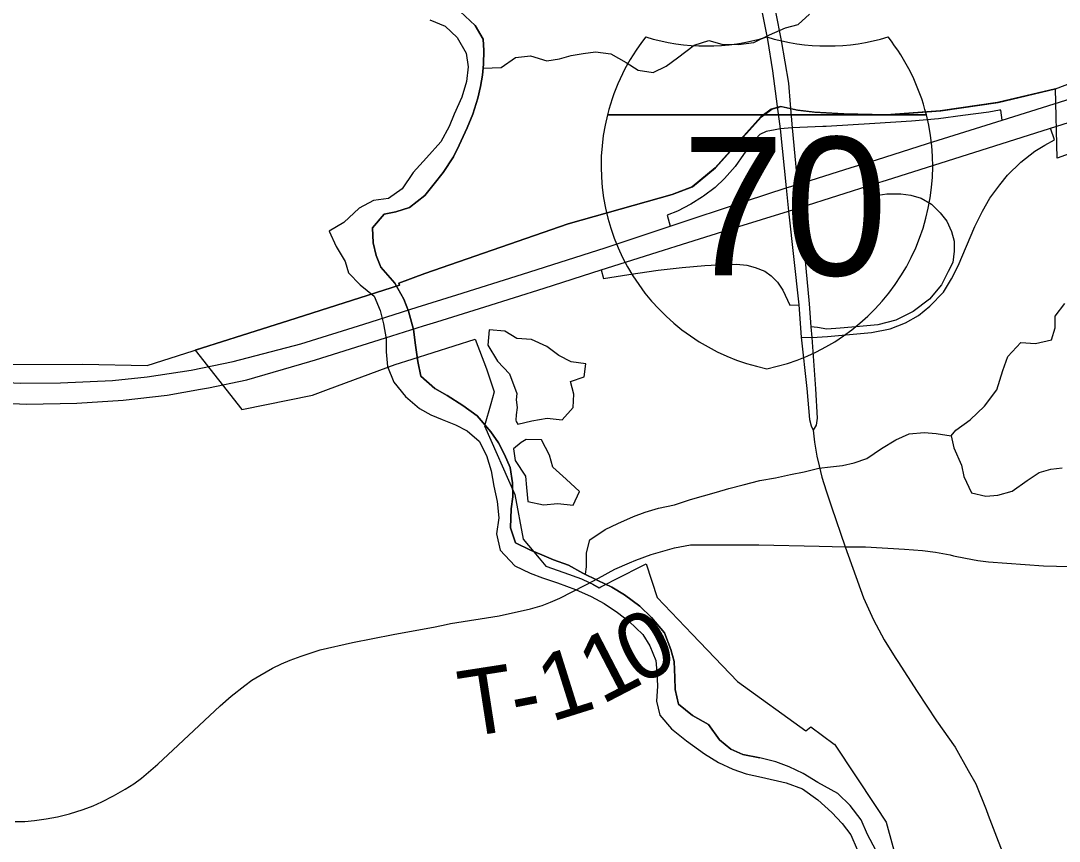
# Model space of a CAD drawing. Extents: x 0 to 34, y 0 to 26.1.
# Drawn here: x 24.227 to 25.117, y 17.231 to 17.933 of the extents above; entities that cross this region are included whole.
import ezdxf

# ---------------------------------------------------------------- set-up
doc = ezdxf.new("R2010")
doc.units = 0
for name, color, linetype in [('GM_X_Interchange_Ramps', 7, 'Continuous'), ('GM_X_Interstate_Location', 7, 'Continuous'), ('GM_X_Interstate_Route', 7, 'Continuous'), ('GM_X_Interstate_Shield', 7, 'Continuous'), ('GM_X_Minor_Lake', 7, 'Continuous'), ('GM_X_Minor_River', 7, 'Continuous'), ('GM_X_State_Route', 7, 'Continuous'), ('GM_X_Township_Road', 7, 'Continuous'), ('GM_X_Township_Road_Text', 7, 'Continuous'), ('SC_Scratch1', 7, 'Continuous')]:
    doc.layers.add(name, color=color, linetype=linetype)

msp = doc.modelspace()

# ---------------------------------------------------------------- linework, layer by layer
at = {"layer": 'GM_X_Interchange_Ramps'}
for p, q in [((24.88787, 17.8414), (24.8775, 17.84071)), ((25.11253, 17.83122), (25.10922, 17.84116))]:
    msp.add_line(p, q, dxfattribs=at)
for points in [[(25.06547, 17.85652), (25.05622, 17.85498), (25.03406, 17.85201), (25.01327, 17.84915), (24.99008, 17.84721), (24.95878, 17.84515), (24.9171, 17.8427)], [(25.06789, 17.84807), (25.0665, 17.85669), (25.06547, 17.85652)], [(24.8775, 17.84071), (24.87337, 17.8399), (24.86567, 17.83839), (24.86018, 17.83585), (24.85359, 17.82859), (24.84628, 17.81854), (24.83897, 17.80837), (24.82994, 17.79809), (24.82183, 17.79044), (24.81188, 17.78301)], [(24.9171, 17.8427), (24.91412, 17.84253), (24.88787, 17.8414)], [(24.89562, 17.66217), (24.90476, 17.66184), (24.91815, 17.66268), (24.95574, 17.66627), (24.97181, 17.66948), (24.98483, 17.67451), (24.99602, 17.68067), (25.00579, 17.68887), (25.01761, 17.70089), (25.02437, 17.7121), (25.03017, 17.72328), (25.04445, 17.75697), (25.05085, 17.77022), (25.05724, 17.7813), (25.06581, 17.79273), (25.07244, 17.80106), (25.08386, 17.81203), (25.09585, 17.82162), (25.10419, 17.82665), (25.11253, 17.83122)], [(24.95935, 17.79377), (24.96164, 17.78393), (24.96884, 17.78496), (24.98106, 17.78496), (24.9894, 17.78382), (24.99847, 17.78125), (25.0071, 17.77605), (25.01475, 17.76874), (25.02035, 17.76143), (25.02435, 17.75263), (25.02663, 17.7443), (25.02663, 17.73584), (25.02538, 17.72625)], [(24.81188, 17.78301), (24.81098, 17.78233), (24.80116, 17.77605), (24.78951, 17.77022), (24.78084, 17.76659), (24.78349, 17.75726)], [(24.72414, 17.71996), (24.72611, 17.71243), (24.74782, 17.71597), (24.77294, 17.71962), (24.7935, 17.72191), (24.81304, 17.72362), (24.82903, 17.72442), (24.84011, 17.72465), (24.8489, 17.72396), (24.85621, 17.72202), (24.86443, 17.71886), (24.86976, 17.71471), (24.87539, 17.70938), (24.87983, 17.70256), (24.88573, 17.68951), (24.89349, 17.68989)], [(25.02538, 17.72625), (25.02161, 17.71837), (25.0159, 17.70706), (25.0055, 17.69484), (24.99157, 17.68421), (24.97672, 17.67679), (24.96118, 17.67279), (24.94565, 17.67131), (24.92897, 17.66994), (24.91766, 17.66914), (24.90967, 17.67051), (24.90396, 17.67119)]]:
    msp.add_lwpolyline(points, dxfattribs=at)
at = {"layer": 'GM_X_Interstate_Route'}
for points in [[(25.06789, 17.84807), (25.15693, 17.87617), (25.22785, 17.89886), (25.29174, 17.91888), (25.38348, 17.94771), (25.44443, 17.96693), (25.52754, 17.99309), (25.59845, 18.0156), (25.67489, 18.03963), (25.75452, 18.0649), (25.81227, 18.08296), (25.85649, 18.09746), (25.896, 18.11232), (25.93026, 18.12665), (25.97711, 18.1485)], [(25.10827, 17.84086), (25.10922, 17.84116), (25.14617, 17.85289), (25.2016, 17.87048), (25.2888, 17.89815), (25.38383, 17.92805), (25.44176, 17.94611), (25.59178, 17.99322)], [(24.95998, 17.81419), (25.00391, 17.82805), (25.06789, 17.84807)], [(24.96878, 17.79677), (25.00932, 17.80966), (25.07329, 17.82968), (25.10827, 17.84086)], [(24.78349, 17.75726), (24.84882, 17.77903), (24.88284, 17.78998), (24.89237, 17.79296), (24.93851, 17.80741), (24.95998, 17.81419)], [(24.77767, 17.73672), (24.78838, 17.74008), (24.83848, 17.75583), (24.88471, 17.77026), (24.89458, 17.77337), (24.95935, 17.79377), (24.96878, 17.79677)], [(23.70781, 17.66191), (23.75214, 17.65819), (23.80544, 17.6541), (23.85589, 17.65009), (23.92512, 17.64485), (24.00805, 17.63871), (24.06073, 17.63461), (24.09899, 17.63159), (24.14846, 17.62785), (24.19286, 17.62465), (24.22685, 17.62296), (24.26111, 17.62313), (24.30578, 17.62509), (24.33549, 17.62829), (24.37296, 17.6339), (24.4089, 17.64129), (24.46692, 17.6565), (24.52084, 17.67341), (24.56675, 17.68782), (24.60057, 17.69841), (24.65689, 17.7163), (24.72754, 17.73872), (24.78349, 17.75726)], [(24.47943, 17.64286), (24.53959, 17.6616), (24.57208, 17.67186), (24.58355, 17.67548), (24.62466, 17.68829), (24.67538, 17.70431), (24.72414, 17.71996), (24.77767, 17.73672)], [(23.70606, 17.64373), (23.89929, 17.62858), (24.01461, 17.61986), (24.08117, 17.61497), (24.18341, 17.60714), (24.23208, 17.60483), (24.27514, 17.60563), (24.31492, 17.60821), (24.35256, 17.61257), (24.38108, 17.61759), (24.38797, 17.6188), (24.42071, 17.62574), (24.47473, 17.6414), (24.47943, 17.64286)]]:
    msp.add_lwpolyline(points, dxfattribs=at)
at = {"layer": 'GM_X_Interstate_Shield'}
for p, q in [((24.72959, 17.85274), (25.00284, 17.85274)), ((25.00284, 17.85274), (24.72959, 17.85274)), ((25.00284, 17.85274), (24.72959, 17.85274))]:
    msp.add_line(p, q, dxfattribs=at)
for centre, start, end in [((24.90173, 17.80921), 141.66896, 165.80665), ((24.81433, 18.08914), 253.00908, 286.99093), ((24.9181, 18.08914), 253.00908, 286.99093), ((24.83071, 17.80921), 14.19335, 38.33104), ((24.90173, 17.80921), 165.80665, 258.46304), ((24.83071, 17.80921), 281.53696, 14.19335)]:
    msp.add_arc(centre, 0.17756, start, end, dxfattribs=at)
at = {"layer": 'GM_X_Minor_Lake'}
for points in [[(24.6529, 17.58781), (24.66497, 17.59065), (24.67787, 17.59276), (24.69071, 17.59144), (24.70032, 17.60193), (24.70087, 17.61332), (24.69799, 17.62437), (24.70978, 17.62838), (24.71108, 17.63937), (24.69861, 17.64106), (24.6881, 17.64652), (24.67761, 17.65426), (24.66445, 17.66014), (24.65197, 17.66107), (24.64184, 17.66728), (24.62824, 17.66861), (24.62729, 17.65533), (24.63542, 17.64156), (24.64586, 17.63078)], [(24.65282, 17.58779), (24.66497, 17.59065), (24.67787, 17.59276), (24.69071, 17.59144), (24.70032, 17.60193), (24.70087, 17.61332), (24.69799, 17.62437), (24.70978, 17.62838), (24.71108, 17.63937), (24.69861, 17.64106), (24.6881, 17.64652), (24.67761, 17.65426), (24.66445, 17.66014), (24.65197, 17.66107), (24.64184, 17.66728), (24.62824, 17.66861), (24.62729, 17.65533), (24.63542, 17.64156), (24.64586, 17.63078)], [(24.64586, 17.63078), (24.65213, 17.61406), (24.65156, 17.60843), (24.65241, 17.60195), (24.65156, 17.59576), (24.65128, 17.59125), (24.65156, 17.59012), (24.6529, 17.58781)], [(24.67306, 17.57422), (24.66001, 17.57463), (24.65579, 17.5721), (24.64911, 17.56658)], [(24.64911, 17.56658), (24.65048, 17.55669), (24.65937, 17.54328), (24.66037, 17.53339), (24.66134, 17.52161), (24.67492, 17.51877), (24.68704, 17.51974), (24.70027, 17.51841), (24.70574, 17.53011), (24.69415, 17.54052), (24.68295, 17.55092), (24.68007, 17.56121), (24.67306, 17.57422)]]:
    msp.add_lwpolyline(points, dxfattribs=at)
at = {"layer": 'GM_X_Minor_River'}
for points in [[(24.57752, 17.93392), (24.59069, 17.92843), (24.60077, 17.9188), (24.60853, 17.9054), (24.61025, 17.89361), (24.60894, 17.8811), (24.60496, 17.86787), (24.59832, 17.85315), (24.59401, 17.84258), (24.58701, 17.82939), (24.57471, 17.81589), (24.56317, 17.80315), (24.55389, 17.78923), (24.54204, 17.78104), (24.52915, 17.77932), (24.51694, 17.77265), (24.5039, 17.76031), (24.49131, 17.75289), (24.49717, 17.7399), (24.50494, 17.72688), (24.50783, 17.71735), (24.5179, 17.70696), (24.52987, 17.69731), (24.53499, 17.68509), (24.53786, 17.67366), (24.53995, 17.66072), (24.54017, 17.64971), (24.54113, 17.63717), (24.54661, 17.6238), (24.55665, 17.61152), (24.56861, 17.6011), (24.57838, 17.59565)], [(24.8603, 17.30209), (24.84558, 17.30495), (24.83542, 17.30926), (24.8257, 17.31737), (24.81605, 17.33041), (24.80253, 17.33819), (24.79056, 17.34785), (24.78771, 17.36042), (24.78748, 17.37067), (24.78692, 17.38434), (24.78403, 17.39463), (24.77856, 17.40913), (24.7674, 17.4222), (24.75732, 17.43183), (24.74421, 17.4415), (24.73333, 17.4481), (24.7213, 17.45397), (24.70852, 17.46022), (24.69613, 17.46684), (24.68333, 17.47158), (24.67355, 17.47589), (24.66377, 17.47982), (24.65099, 17.48607), (24.64663, 17.49904), (24.64724, 17.51535), (24.64853, 17.52558), (24.64831, 17.53736), (24.64623, 17.55067), (24.64147, 17.56175), (24.63632, 17.57169), (24.62964, 17.58127), (24.6181, 17.59472), (24.60574, 17.60362), (24.59224, 17.61216), (24.58173, 17.61838), (24.56977, 17.6288), (24.5673, 17.64136), (24.56523, 17.65544), (24.56353, 17.66875), (24.55921, 17.68437), (24.55519, 17.69468), (24.54744, 17.70845), (24.53553, 17.72229), (24.5315, 17.73221), (24.52901, 17.74287), (24.52843, 17.75579), (24.53844, 17.76742), (24.54831, 17.76956), (24.56009, 17.7732), (24.57311, 17.78365), (24.58119, 17.7934), (24.5889, 17.80317), (24.5978, 17.81671), (24.60248, 17.82652), (24.60951, 17.84161), (24.61422, 17.85331), (24.61857, 17.86692), (24.62099, 17.87675), (24.62264, 17.8866), (24.62353, 17.89608), (24.6237, 17.90785), (24.62308, 17.91735), (24.61643, 17.92921), (24.60336, 17.94116)], [(24.60336, 17.94116), (24.61643, 17.92921), (24.62308, 17.91735), (24.6237, 17.90785), (24.62353, 17.89608), (24.62264, 17.8866), (24.62099, 17.87675), (24.61857, 17.86692), (24.61422, 17.85331), (24.60951, 17.84161), (24.60248, 17.82652), (24.5978, 17.81671), (24.5889, 17.80317), (24.58119, 17.7934), (24.57311, 17.78365), (24.56009, 17.7732), (24.54831, 17.76956), (24.53844, 17.76742), (24.52843, 17.75579), (24.52901, 17.74287), (24.5315, 17.73221), (24.53553, 17.72229), (24.54744, 17.70845), (24.55519, 17.69468), (24.55921, 17.68437), (24.56353, 17.66875), (24.56523, 17.65544), (24.5673, 17.64136), (24.56977, 17.6288), (24.58173, 17.61838), (24.59224, 17.61216), (24.60574, 17.60362), (24.6181, 17.59472), (24.62964, 17.58127), (24.63632, 17.57169), (24.64147, 17.56175), (24.64623, 17.55067), (24.64831, 17.53736), (24.64853, 17.52558), (24.64724, 17.51535), (24.64663, 17.49904), (24.65099, 17.48607), (24.66377, 17.47982), (24.67355, 17.47589), (24.68333, 17.47158), (24.69613, 17.46684), (24.70852, 17.46022), (24.7213, 17.45397), (24.73333, 17.4481), (24.74421, 17.4415), (24.75732, 17.43183), (24.7674, 17.4222), (24.77856, 17.40913), (24.78403, 17.39463), (24.78692, 17.38434), (24.78748, 17.37067), (24.78771, 17.36042), (24.79056, 17.34785), (24.80253, 17.33819), (24.81605, 17.33041), (24.8257, 17.31737), (24.83542, 17.30926), (24.84558, 17.30495), (24.8603, 17.30209)], [(24.62321, 17.89266), (24.63863, 17.89322), (24.65086, 17.90178), (24.66375, 17.90312), (24.67769, 17.89875), (24.68869, 17.9005), (24.69857, 17.9034), (24.70881, 17.90515), (24.71943, 17.90652), (24.73265, 17.90482), (24.74579, 17.89743), (24.75591, 17.89083), (24.76875, 17.88876), (24.7798, 17.8943), (24.78974, 17.90137), (24.8039, 17.91219), (24.81645, 17.91619), (24.82775, 17.913), (24.84175, 17.9128), (24.85503, 17.91452), (24.86837, 17.92117), (24.88207, 17.92705), (24.89309, 17.92994), (24.90268, 17.93892)], [(25.02393, 17.57771), (25.02816, 17.58259), (25.0404, 17.59153), (25.05267, 17.60313), (25.06309, 17.61703), (25.06825, 17.63366), (25.07258, 17.64575), (25.08373, 17.65775), (25.0962, 17.65682), (25.10987, 17.66004), (25.11305, 17.67025), (25.11319, 17.68012), (25.12129, 17.69102)], [(24.57838, 17.59565), (24.58816, 17.59172), (24.59945, 17.58701), (24.60959, 17.58193), (24.61968, 17.57306), (24.62594, 17.56082), (24.62992, 17.54786), (24.63238, 17.53454), (24.63522, 17.52159), (24.63654, 17.50753), (24.63445, 17.49389), (24.63766, 17.4798), (24.65033, 17.46634), (24.66349, 17.46008), (24.67403, 17.45614), (24.68683, 17.45179), (24.70227, 17.44626), (24.7158, 17.44), (24.7267, 17.43415), (24.73832, 17.4264), (24.74805, 17.41905), (24.76, 17.40749), (24.76592, 17.39792), (24.77103, 17.38532), (24.77203, 17.37544), (24.77261, 17.36328), (24.77167, 17.35039), (24.77453, 17.33858), (24.78458, 17.32667), (24.79731, 17.31663), (24.81266, 17.30541), (24.82467, 17.29802), (24.83707, 17.29216), (24.84837, 17.28821), (24.86157, 17.28537), (24.8827, 17.28052), (24.89663, 17.27539), (24.90974, 17.2661), (24.9217, 17.2553), (24.93064, 17.24569), (24.93807, 17.23609), (24.94357, 17.22349)], [(24.71069, 17.45915), (24.71163, 17.46549), (24.7118, 17.47763), (24.7146, 17.4886), (24.7276, 17.49754), (24.73865, 17.5027), (24.75198, 17.50859), (24.76187, 17.51225), (24.77328, 17.51588), (24.78694, 17.51873), (24.80063, 17.5231), (24.81203, 17.52636), (24.82305, 17.52962), (24.83368, 17.53251), (24.84584, 17.53576), (24.86027, 17.53936), (24.87355, 17.54183), (24.88646, 17.54469), (24.89822, 17.5468), (24.91076, 17.55005), (24.92061, 17.55105), (24.93085, 17.55243), (24.9411, 17.55456), (24.95174, 17.55821), (24.96436, 17.56677), (24.97657, 17.57419), (24.988, 17.57935), (25.00089, 17.58069), (25.01109, 17.57979), (25.02393, 17.57771), (25.02643, 17.56743), (25.03303, 17.55253), (25.03479, 17.54301), (25.0414, 17.52887), (25.05385, 17.52604), (25.06408, 17.52704), (25.07623, 17.53029), (25.08923, 17.5396), (25.09955, 17.54629), (25.10943, 17.54919), (25.11928, 17.5502)], [(24.95946, 17.22289), (24.95246, 17.23628), (24.94696, 17.24888), (24.93767, 17.26116), (24.92685, 17.27155), (24.90995, 17.2809), (24.89719, 17.28867), (24.88516, 17.29415), (24.87387, 17.29848), (24.8603, 17.30209)]]:
    msp.add_lwpolyline(points, dxfattribs=at)
at = {"layer": 'GM_X_State_Route'}
msp.add_line((24.87505, 17.85975), (24.8775, 17.84071), dxfattribs=at)
for points in [[(24.81149, 18.11961), (24.81638, 18.11571), (24.81918, 18.11038), (24.85219, 18.01386), (24.85816, 17.99268), (24.8673, 17.96357), (24.87345, 17.94087), (24.87851, 17.91641), (24.88458, 17.8797), (24.88619, 17.86158), (24.88787, 17.8414)], [(24.84203, 18.0108), (24.84756, 17.99237), (24.85647, 17.96242), (24.86215, 17.93999), (24.86683, 17.91711), (24.87114, 17.89022), (24.87505, 17.85975)], [(24.8775, 17.84071), (24.88284, 17.78998), (24.88471, 17.77026), (24.89349, 17.68989), (24.89562, 17.66217)], [(24.88787, 17.8414), (24.89237, 17.79296), (24.89458, 17.77337), (24.90252, 17.69065), (24.90396, 17.67119), (24.90476, 17.66184), (24.90785, 17.61789), (24.90938, 17.59285), (24.90854, 17.58694), (24.90577, 17.58263)], [(24.89562, 17.66217), (24.9004, 17.61812), (24.90262, 17.59162), (24.90424, 17.58617), (24.90577, 17.58263)], [(24.90577, 17.58263), (24.90693, 17.57219), (24.90908, 17.56044), (24.91092, 17.55199), (24.91338, 17.54239), (24.91699, 17.53064), (24.92167, 17.51705), (24.93314, 17.48276)], [(24.93314, 17.48276), (24.95072, 17.48275), (24.98405, 17.48078), (24.99952, 17.47967), (25.0106, 17.4782), (25.02313, 17.47569), (25.02619, 17.47503)], [(24.93314, 17.48276), (24.94901, 17.4389), (24.95743, 17.42026), (24.96672, 17.40294), (24.97622, 17.38794), (24.97835, 17.38461)], [(25.02619, 17.47503), (25.03637, 17.47283), (25.04693, 17.47105), (25.05613, 17.46992), (25.10325, 17.4665), (25.15853, 17.46485), (25.16063, 17.46487)], [(24.97835, 17.38461), (24.99481, 17.3588), (25.01149, 17.33367), (25.02754, 17.31107), (25.03873, 17.29122), (25.04528, 17.27961), (25.05402, 17.25759)], [(25.05402, 17.25759), (25.05584, 17.253), (25.07337, 17.20696), (25.08519, 17.17719), (25.09638, 17.151), (25.12531, 17.08427)]]:
    msp.add_lwpolyline(points, dxfattribs=at)
at = {"layer": 'GM_X_Township_Road'}
for points in [[(24.74856, 17.4689), (24.75402, 17.4712), (24.76717, 17.47598), (24.7872, 17.48186), (24.80087, 17.48448), (24.82231, 17.48449), (24.85923, 17.48432), (24.91085, 17.4831), (24.93314, 17.48276)], [(24.72184, 17.45597), (24.73583, 17.46353), (24.74856, 17.4689)], [(24.59137, 17.41618), (24.59514, 17.41699), (24.63685, 17.42352), (24.66376, 17.42969), (24.67357, 17.43244), (24.68092, 17.43528), (24.68881, 17.43885), (24.71047, 17.44983), (24.72184, 17.45597)], [(24.22217, 17.24736), (24.23064, 17.2475), (24.23883, 17.24819), (24.24897, 17.24971), (24.25854, 17.25152), (24.26884, 17.25408), (24.28042, 17.25772), (24.28908, 17.26096), (24.29643, 17.26429), (24.30655, 17.26952), (24.31658, 17.27514), (24.32392, 17.27984), (24.33058, 17.28455), (24.34458, 17.29653), (24.36181, 17.3127), (24.39799, 17.34654), (24.40742, 17.35484), (24.4189, 17.36397), (24.42511, 17.3684), (24.43175, 17.37245), (24.4427, 17.37866), (24.45053, 17.38241), (24.45791, 17.3856), (24.46732, 17.38904), (24.48341, 17.39456), (24.51135, 17.40064), (24.54596, 17.40747), (24.58194, 17.41415), (24.59137, 17.41618)]]:
    msp.add_lwpolyline(points, dxfattribs=at)
at = {"layer": 'SC_Scratch1'}
for points in [[(24.21628, 17.63892), (24.28027, 17.63909), (24.33538, 17.63804), (24.38805, 17.65478), (24.45669, 17.6766), (24.55148, 17.70677), (24.55091, 17.70857), (24.5732, 17.71668), (24.69595, 17.75932), (24.78512, 17.78445), (24.80251, 17.79084), (24.82219, 17.80736), (24.86154, 17.85094), (24.87032, 17.85761), (24.8784, 17.85973), (24.89281, 17.85656), (24.90721, 17.85481), (24.9325, 17.8534), (24.96869, 17.85269), (25.01509, 17.85599), (25.0643, 17.86314), (25.11341, 17.8748), (25.23822, 17.92241)], [(25.1981, 17.84577), (25.11483, 17.81552), (25.11341, 17.8748), (25.06389, 17.86314), (25.01468, 17.85599), (24.96828, 17.85269), (24.93209, 17.8534), (24.9068, 17.85481), (24.89239, 17.85656), (24.87799, 17.85973), (24.86991, 17.85761), (24.86113, 17.85094), (24.82178, 17.80736), (24.8021, 17.79084), (24.78512, 17.78445), (24.69595, 17.75932), (24.5732, 17.71668), (24.55091, 17.70857), (24.55148, 17.70677), (24.45669, 17.6766), (24.3765, 17.65111), (24.41657, 17.60028), (24.47691, 17.61262), (24.4908, 17.61776), (24.54791, 17.63893), (24.56228, 17.64348), (24.61644, 17.66062), (24.62606, 17.63519), (24.63254, 17.61555), (24.62961, 17.60521), (24.62421, 17.58628), (24.65025, 17.52749), (24.6574, 17.48922), (24.67106, 17.47301), (24.67696, 17.466), (24.69227, 17.46055), (24.70747, 17.45513), (24.714, 17.45219), (24.71712, 17.45078), (24.72255, 17.44763), (24.72404, 17.44839), (24.75773, 17.46565), (24.76275, 17.46798), (24.77234, 17.43939), (24.80233, 17.40789), (24.8409, 17.36738), (24.89956, 17.32501), (24.90379, 17.32846), (24.92385, 17.31376), (24.92402, 17.31364), (24.92407, 17.31356), (24.95943, 17.26044), (24.96841, 17.24695), (24.9806, 17.20212)]]:
    msp.add_lwpolyline(points, dxfattribs=at)

# ---------------------------------------------------------------- texts
at = {"layer": 'GM_X_Interstate_Location'}
for s in ['-', '.', ',']:
    msp.add_text(s, height=0.000189, dxfattribs=at).set_placement((24.86619, 17.77719))
msp.add_text('70', height=0.000189, rotation=0.00001, dxfattribs=at).set_placement((24.8275, 17.73798))
at = {"layer": 'GM_X_Interstate_Shield'}
msp.add_text('70', height=0.118371, dxfattribs=at).set_placement((24.79348, 17.71514))
at = {"layer": 'GM_X_Township_Road_Text'}
for s, rotation, p in [('0', 27.4851, (24.75572, 17.36321)), ('1', 27.4364, (24.72461, 17.34706)), ('1', 17.41487, (24.68122, 17.33245)), ('T', 8.82469, (24.60728, 17.31937)), ('-', 11.0156, (24.65161, 17.32629))]:
    msp.add_text(s, height=0.05682, rotation=rotation, dxfattribs=at).set_placement(p)

doc.saveas('drawing.dxf')
